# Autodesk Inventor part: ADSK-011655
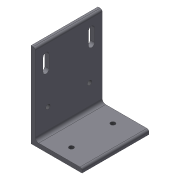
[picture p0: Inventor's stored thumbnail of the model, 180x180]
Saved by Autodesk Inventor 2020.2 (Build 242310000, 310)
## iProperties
Part Number: ADSK-011655
Description: BRKT24,AH,AX,50,30,02,040,PAD MOUNT
Document SubType Name: Modeling
Material: Pearson HRS
Density: 7.83 g/cm^3
Created: 2017-03
Appearance: Métal - Acier
Mass: 949.465 g
Surface Area: 428.079 cm^2
Volume: 121.26 cm^3
Control State: 0
Master: False
Checked Out: False
Shininess: 0.0
Length Units: 11269
Angle Units: 11279
Time Units: 11290
Mass Units: 11283
Length Display Precision: 3
Angle Display Precision: 2
Compacted: True
Cutlength: 4
Material Desc: ANGLE,HRS,.250X5.00X3.00
Material_Number: A084067
Dimensions: 127x100x76,2 mm
Mass: 0,949 kg
VLT_Material: Pearson HRS
Density: 0.0
Volumn: 0.0
Area: 0.0
PropertySet Name: Model Information
Revision Number: -
Title: BRKT24,AH,AX,50,30,02,040,PAD MOUNT
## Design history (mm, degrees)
node "Element2:1"
node "Extrusion1" dims "d16" = 25.4, "d17" = 0
  sketch "Sketch3"
    geometry: L1 (0, 127)-(100, 127) reference; L2 (11.5, 109)-(20.5, 109); L3 (20.5, 109)-(20.5, 90); L4 (20.5, 90)-(11.5, 90); L5 (11.5, 90)-(11.5, 109); L6 (79.5, 109)-(88.5, 109); L7 (88.5, 109)-(88.5, 90); L8 (88.5, 90)-(79.5, 90); L9 (79.5, 90)-(79.5, 109); L10 (16, 109)-(16, 90); L11 (84, 109)-(84, 90); L12 (84, 99.5)-(16, 99.5); A1 r 4.5 centre (16, 109) between (20.5, 109) and (11.5, 109); A2 r 4.5 centre (16, 90) between (11.5, 90) and (20.5, 90); A3 r 4.5 centre (84, 109) between (88.5, 109) and (79.5, 109); A4 r 4.5 centre (84, 90) between (79.5, 90) and (88.5, 90); 2 further points
    constraints: 22 end point, 8 point on circle, 4 centre point, 4 midpoint, 4 parallel, 4 tangent, 2 equal length, 2 horizontal, 2 perpendicular, 1 horizontal alignment, 1 vertical, 1 vertical alignment
    dimensions: "d11" = 19 distance of L2.end L3.end; "d12" = 9 distance of L2.start L2.end; "d38" = 27.5 distance between parallel lines of L1 L12; "d39" = 68 distance of L12.start L12.end
node "Hole1" dims "d22" = 6.647, "d23" = 9.525, "d24" = 6.35, "d25" = 60 deg, "d26" = 19.05, "d27" = 118 deg, "d42" = 16
  sketch "Sketch4"
    geometry: L1 (19, 41.35)-(81, 41.35); L2 (0, 6.35)-(100, 6.35) reference; 2 further points
    constraints: 2 end point, 1 horizontal, 1 midpoint, 1 vertical alignment
    dimensions: "d41" = 62 distance of L1.start L1.end; "d46" = 35 distance between parallel lines of L2 L1
node "Hole2" dims "d32" = 6.647, "d33" = 9.525, "d34" = 6.35, "d35" = 60 deg, "d36" = 19.05, "d37" = 118 deg, "d44" = 16
  sketch "Sketch5"
    geometry: L1 (0, 0)-(76.2, 0) reference; L2 (76.2, 0)-(76.2, 100) reference; L3 (41.35, 19)-(41.35, 81); 3 further points
    constraints: 3 midpoint, 2 end point, 1 horizontal alignment, 1 vertical
    dimensions: "d43" = 62 distance of L3.start L3.end; "d45" = 3.25 distance from line of point (38.1, 0) L3
node "Solide1"
node "Corps solides"
node "Corps surfaciques"
sketch "Sketch1"
  geometry: L1 (100, 0)-(100, 127) reference; L2 (0, 127)-(100, 127) reference; L3 (0, 127)-(0, 0) reference; L4 (0, 0)-(100, 0) reference
sketch "Sketch2"
  geometry: L1 (32.408, 38.758)-(108.608, 38.758); L2 (32.408, 165.758)-(32.408, 38.758); L3 (38.758, 162.583)-(38.758, 50.188); L4 (43.838, 45.108)-(105.433, 45.108); L5 (32.408, 165.758)-(35.583, 165.758); L6 (108.608, 41.933)-(108.608, 38.758); A1 r 3.175 centre (35.583, 162.583) between (38.758, 162.583) and (35.583, 165.758); A2 r 3.175 centre (105.433, 41.933) between (108.608, 41.933) and (105.433, 45.108); A3 r 5.08 centre (43.838, 50.188) between (38.758, 50.188) and (43.838, 45.108); 1 further point
  constraints: 12 end point, 6 point on circle, 6 tangent, 3 centre point, 1 coincident, 1 equal radius, 1 horizontal, 1 perpendicular, 1 other
  dimensions: "d0" = 6.35 distance between parallel lines of L2 L3 (derived); "d3" = 3.175 radius of A1 (derived); "d4" = 5.08 radius of A3 (derived); "d1" = 127 distance between parallel lines of L1 L5 (derived); "d2" = 76.2 distance between parallel lines of L6 L2 (derived)
